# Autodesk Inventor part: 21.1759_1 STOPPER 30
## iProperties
Created: 2007-03
Part Number: 21.1759_1 STOPPER 30
Document SubType Name: Modeling
Designer: Andy Moles
Material: Rubber
Mass: 20.2823 g
Surface Area: 45.4274 cm^2
Volume: 21.8089 cm^3
Density: 0.93 g/cm^3
Author: Andy Moles
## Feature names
1. Extrusion1
2. Extrusion2
